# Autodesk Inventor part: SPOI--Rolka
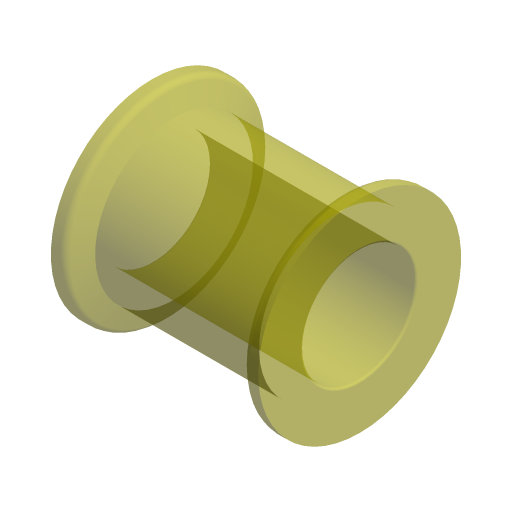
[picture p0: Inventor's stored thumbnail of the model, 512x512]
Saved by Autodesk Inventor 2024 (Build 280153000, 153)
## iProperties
Company: ATC
Shininess: 20.0
Length Units: 11269
Angle Units: 11279
Time Units: 11290
Mass Units: 11283
Length Display Precision: 3
Angle Display Precision: 2
Compacted: True
Created: 2023-03
Part Number: SPOI--Rolka
Document SubType Name: Modeling
Designer: Andrzej Jaskulski
Material: Kurs-AJ
Density: 1 g/cm^3
Mass: 26.4779 g
Surface Area: 118.848 cm^2
Volume: 26.4779 cm^3
Appearance: Przezroczyste — żółte
Checked By: A.J.
Engr Approved By: Andrzej Jaskulski
Mfg Approved By: Andrzej Jaskulski
Authority: A.J.
Density: 0.0
Volumn: 0.0
Area: 0.0
PropertySet Name: Model Information
Control State: 0
Master: False
Checked Out: False
Title: A.J.: Kurs R2024-MEP
Author: Andrzej Jaskulski
Revision Number: 1/24
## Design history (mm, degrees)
node "Revolution1" dims "d7" = 90 deg
node "Fillet1" dims "d8" = 1.5
node "Fillet2" dims "d11" = 0.5
node "Bryła1"
node "Korpusy bryłowe"
node "Korpusy powierzchniowe"
sketch "Sketch1"
  geometry: L1 (20, -40)-(66, -40); L2 (66, -40)-(66, -30); L3 (66, -30)-(63, -30); L4 (63, -30)-(61.18, -35); L5 (61.18, -35)-(24.82, -35); L6 (24.82, -35)-(23, -30); L7 (23, -30)-(20, -30); L8 (20, -30)-(20, -40); L9 (14, -52.5)-(73, -52.5)
  constraints: 18 end point, 4 parallel, 3 equal length, 2 perpendicular, 1 horizontal, 1 other
  dimensions: "d0" = 10 distance of L1.end L2.end; "d1" = 5 distance between parallel lines of L1 L5; "d2" = 3 distance of L2.end L3.end; "d4" = 110 deg angle of L5 L4; "d5" = 46 distance of L2.end L7.end (derived); "d6" = 12.5 distance between parallel lines of L9 L1
